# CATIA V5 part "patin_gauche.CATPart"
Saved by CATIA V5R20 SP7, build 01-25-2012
Part number: patin_gauche
Bounding box of the stored display mesh (mm): x -574.226 to -296.558, y -188.302 to 188.302, z -20 to 0
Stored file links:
  U:\IAO\thinkmotion catia2\patin_gauche.CATPart
  U:\IAO\thinkmotion catia2\Ass_862_adubourgno.CATProduct
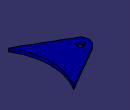
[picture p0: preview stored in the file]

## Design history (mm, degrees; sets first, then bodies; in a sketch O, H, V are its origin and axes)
Set1
  Plane1: linked copy from another document
  Point1 "I": linked copy from another document
  Point2 "N": linked copy from another document
Body1 (main body)
  Sketch1 on Plane1, origin (0, 0, 0), H (1, 0, 0), V (0, 1, 0)
    construction line L1 (-350, 0) -> (-524.226, 0)
    point P1 (-350, 0)
    point P2 (-524.226, 0)
    reference projected point E1 (-524.226, 0) from Point1
    reference projected point E2 (-350, 0) from Point2
    axis line L2 (-524.226, 0) -> (-564.4811, 47.9742)
    point P3 (-524.226, 0)
    point P4 (-564.4811, 47.9742)
    reference projected point E3 (-524.226, 0) from Point1
    point P5 (-564.4811, -47.9742)
    point P6 (-524.226, 0)
    construction line L3 (-524.226, 0) -> (-564.4811, -47.9742)
    arc A1 centre (-524.226, 0) radius 50 from (-556.3654, 38.3023) to (-556.3654, -38.3022) ccw
    point P7 (-524.226, 0)
    point P8 (-556.3654, -38.3022)
    point P9 (-556.3654, 38.3023)
    reference projected point E4 (-524.226, 0) from Point1
    line L4 (-556.3654, 38.3023) -> (-296.5578, 188.3023)
    point P10 (-556.3654, 38.3023)
    point P11 (-296.5578, 188.3023)
    point P12 (-296.5578, -188.3023)
    point P13 (-556.3654, -38.3023)
    line L5 (-556.3654, -38.3023) -> (-296.5578, -188.3023)
    arc A2 centre (-1.5286, 0) radius 350 from (-296.5578, 188.3023) to (-296.5578, -188.3023) ccw
    point P14 (-1.5286, 0)
    circle A3 centre (-524.226, 0) radius 20
    point P15 (-524.226, 0)
    reference projected point E5 (-524.226, 0) from Point1
    distance E1 P2 = 0
    distance E2 P1 = 0
    distance E3 P3 = 0
    angle L1 L2 = 130
    distance E4 P7 = 0
    radius A1 = 50
    angle L4 L1 = 150
    length L4 = 300
    radius A2 = 350
    radius A3 = 20
    distance E5 P15 = 0
    symmetry: P4 P5 L1, P3 P6 L1, L2 L3 L1, P11 P12 L1, P10 P13 L1, L4 L5 L1
    coincidence: P8 L3, P9 L2, P10 A1, P10 L2, P14 H, P9 P10
  Pad1: profile Sketch1, direction (0, 0, -1), length 20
